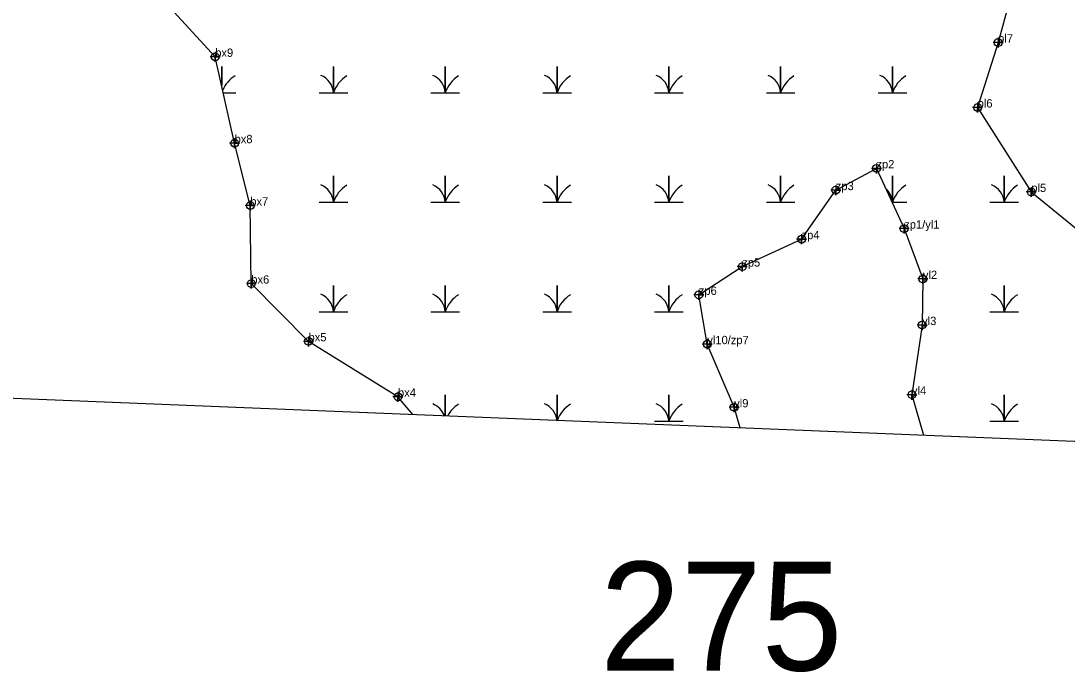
# Model space of a CAD drawing. Extents: x 2071991 to 2268989, y 436479 to 469629.
# Drawn here: x 2233643 to 2234271, y 437646 to 438038 of the extents above; entities that cross this region are included whole.
import ezdxf

# ---------------------------------------------------------------- set-up
doc = ezdxf.new("R2010")
doc.units = 0
for name, color, linetype in [('approx_PSA', 7, 'Continuous'), ('Default', 7, 'Continuous'), ('Exist Environmental Wetland Boundary', 7, 'Continuous'), ('Exist Environmental Wetland Boundary Cogo Comment', 7, 'Continuous'), ('Exist Environmental Wetland Boundary Cogo Point CELL', 7, 'Continuous'), ('Exist Hydro Swamp or Marsh', 7, 'Continuous')]:
    doc.layers.add(name, color=color, linetype=linetype)

msp = doc.modelspace()

# ---------------------------------------------------------------- linework, layer by layer
at = {"layer": 'approx_PSA'}
msp.add_line((2234896.82, 437759.82), (2232283.57, 437865.3), dxfattribs=at)
at = {"layer": 'Exist Environmental Wetland Boundary'}
for points in [[(2234279.17, 438159.32), (2234258.17, 438132.28), (2234242.26, 438069.78), (2234230.04, 438024.51), (2234217.72, 437985.47), (2234249.98, 437934.73), (2234302.96, 437891.47)], [(2233878.1, 437800.94), (2233869.26, 437811.67), (2233815.49, 437844.98), (2233781.11, 437879.68), (2233780.48, 437926.57), (2233771.05, 437964.06), (2233759.41, 438015.96), (2233727.92, 438050.47), (2233767.76, 438077.73), (2233779.58, 438110.39), (2233791.43, 438130.77), (2233736.36, 438122.5), (2233685.39, 438115.35), (2233620.22, 438102.5)], [(2234074.95, 437792.99), (2234071.38, 437805.34), (2234055.2, 437843.29), (2234050.1, 437872.92), (2234076.23, 437889.9), (2234111.89, 437906.38), (2234132.43, 437935.84), (2234156.88, 437948.92), (2234173.58, 437912.73), (2234184.81, 437882.46), (2234184.34, 437854.8), (2234178.23, 437812.94), (2234185.11, 437788.55)]]:
    msp.add_lwpolyline(points, dxfattribs=at)
at = {"layer": 'Exist Environmental Wetland Boundary Cogo Point CELL'}
for points in [[(2234230.04, 438027.51), (2234230.04, 438021.51), (2234230.04, 438024.51), (2234233.04, 438024.51), (2234227.04, 438024.51)], [(2233759.41, 438018.96), (2233759.41, 438012.96), (2233759.41, 438015.96), (2233762.41, 438015.96), (2233756.41, 438015.96)], [(2234217.72, 437988.47), (2234217.72, 437982.47), (2234217.72, 437985.47), (2234220.72, 437985.47), (2234214.72, 437985.47)], [(2233771.05, 437967.06), (2233771.05, 437961.06), (2233771.05, 437964.06), (2233774.05, 437964.06), (2233768.05, 437964.06)], [(2234156.88, 437951.92), (2234156.88, 437945.92), (2234156.88, 437948.92), (2234159.88, 437948.92), (2234153.88, 437948.92)], [(2234132.43, 437938.84), (2234132.43, 437932.84), (2234132.43, 437935.84), (2234135.43, 437935.84), (2234129.43, 437935.84)], [(2234249.98, 437937.73), (2234249.98, 437931.73), (2234249.98, 437934.73), (2234252.98, 437934.73), (2234246.98, 437934.73)], [(2233780.48, 437929.57), (2233780.48, 437923.57), (2233780.48, 437926.57), (2233783.48, 437926.57), (2233777.48, 437926.57)], [(2234173.58, 437915.73), (2234173.58, 437909.73), (2234173.58, 437912.73), (2234176.58, 437912.73), (2234170.58, 437912.73)], [(2234111.89, 437909.38), (2234111.89, 437903.38), (2234111.89, 437906.38), (2234114.89, 437906.38), (2234108.89, 437906.38)], [(2234076.23, 437892.9), (2234076.23, 437886.9), (2234076.23, 437889.9), (2234079.23, 437889.9), (2234073.23, 437889.9)], [(2233781.11, 437882.68), (2233781.11, 437876.68), (2233781.11, 437879.68), (2233784.11, 437879.68), (2233778.11, 437879.68)], [(2234184.81, 437885.46), (2234184.81, 437879.46), (2234184.81, 437882.46), (2234187.81, 437882.46), (2234181.81, 437882.46)], [(2234050.1, 437875.92), (2234050.1, 437869.92), (2234050.1, 437872.92), (2234053.1, 437872.92), (2234047.1, 437872.92)], [(2234184.34, 437857.8), (2234184.34, 437851.8), (2234184.34, 437854.8), (2234187.34, 437854.8), (2234181.34, 437854.8)], [(2233815.49, 437847.98), (2233815.49, 437841.98), (2233815.49, 437844.98), (2233818.49, 437844.98), (2233812.49, 437844.98)], [(2234055.2, 437846.29), (2234055.2, 437840.29), (2234055.2, 437843.29), (2234058.2, 437843.29), (2234052.2, 437843.29)], [(2233869.26, 437814.67), (2233869.26, 437808.67), (2233869.26, 437811.67), (2233872.26, 437811.67), (2233866.26, 437811.67)], [(2234178.23, 437815.94), (2234178.23, 437809.94), (2234178.23, 437812.94), (2234181.23, 437812.94), (2234175.23, 437812.94)], [(2234071.38, 437808.34), (2234071.38, 437802.34), (2234071.38, 437805.34), (2234074.38, 437805.34), (2234068.38, 437805.34)]]:
    msp.add_lwpolyline(points, dxfattribs=at)
for centre in [(2234230.04, 438024.51), (2233759.41, 438015.96), (2234217.72, 437985.47), (2233771.05, 437964.06), (2234156.88, 437948.92), (2234132.43, 437935.84), (2234249.98, 437934.73), (2233780.48, 437926.57), (2234173.58, 437912.73), (2234111.89, 437906.38), (2234076.23, 437889.9), (2233781.11, 437879.68), (2234184.81, 437882.46), (2234050.1, 437872.92), (2234184.34, 437854.8), (2233815.49, 437844.98), (2234055.2, 437843.29), (2233869.26, 437811.67), (2234178.23, 437812.94), (2234071.38, 437805.34)]:
    msp.add_circle(centre, 2.34, dxfattribs=at)
at = {"layer": 'Exist Hydro Swamp or Marsh'}
msp.add_line((2233764.26, 437994.35), (2233771.89, 437994.35), dxfattribs=at)
for points in [[(2233763.28, 437998.69), (2233763.28, 438010.13), (2233763.28, 437998.69)], [(2233821.89, 437994.35), (2233830.49, 437994.35), (2233830.49, 438010.13), (2233830.49, 437994.35), (2233839.09, 437994.35)], [(2233889.09, 437994.35), (2233897.69, 437994.35), (2233897.69, 438010.13), (2233897.69, 437994.35), (2233906.29, 437994.35)], [(2233956.29, 437994.35), (2233964.89, 437994.35), (2233964.89, 438010.13), (2233964.89, 437994.35), (2233973.5, 437994.35)], [(2234023.5, 437994.35), (2234032.1, 437994.35), (2234032.1, 438010.13), (2234032.1, 437994.35), (2234040.7, 437994.35)], [(2234090.7, 437994.35), (2234099.3, 437994.35), (2234099.3, 438010.13), (2234099.3, 437994.35), (2234107.9, 437994.35)], [(2234157.9, 437994.35), (2234166.5, 437994.35), (2234166.5, 438010.13), (2234166.5, 437994.35), (2234175.11, 437994.35)], [(2233821.89, 437928.57), (2233830.49, 437928.57), (2233830.49, 437944.35), (2233830.49, 437928.57), (2233839.09, 437928.57)], [(2233889.09, 437928.57), (2233897.69, 437928.57), (2233897.69, 437944.35), (2233897.69, 437928.57), (2233906.29, 437928.57)], [(2233956.29, 437928.57), (2233964.89, 437928.57), (2233964.89, 437944.35), (2233964.89, 437928.57), (2233973.5, 437928.57)], [(2234023.5, 437928.57), (2234032.1, 437928.57), (2234032.1, 437944.35), (2234032.1, 437928.57), (2234040.7, 437928.57)], [(2234090.7, 437928.57), (2234099.3, 437928.57), (2234099.3, 437944.35), (2234099.3, 437928.57), (2234107.9, 437928.57)], [(2234166.27, 437928.57), (2234166.5, 437928.57), (2234166.5, 437944.35), (2234166.5, 437928.57), (2234175.11, 437928.57)], [(2234225.11, 437928.57), (2234233.71, 437928.57), (2234233.71, 437944.35), (2234233.71, 437928.57), (2234242.31, 437928.57)], [(2233821.89, 437862.79), (2233830.49, 437862.79), (2233830.49, 437878.57), (2233830.49, 437862.79), (2233839.09, 437862.79)], [(2233889.09, 437862.79), (2233897.69, 437862.79), (2233897.69, 437878.57), (2233897.69, 437862.79), (2233906.29, 437862.79)], [(2233956.29, 437862.79), (2233964.89, 437862.79), (2233964.89, 437878.57), (2233964.89, 437862.79), (2233973.5, 437862.79)], [(2234023.5, 437862.79), (2234032.1, 437862.79), (2234032.1, 437878.57), (2234032.1, 437862.79), (2234040.7, 437862.79)], [(2234225.11, 437862.79), (2234233.71, 437862.79), (2234233.71, 437878.57), (2234233.71, 437862.79), (2234242.31, 437862.79)], [(2233897.69, 437800.15), (2233897.69, 437812.79), (2233897.69, 437800.15)], [(2233964.89, 437797.43), (2233964.89, 437812.79), (2233964.89, 437797.43)], [(2234023.5, 437797.01), (2234032.1, 437797.01), (2234032.1, 437812.79), (2234032.1, 437797.01), (2234040.7, 437797.01)], [(2234225.11, 437797.01), (2234233.71, 437797.01), (2234233.71, 437812.79), (2234233.71, 437797.01), (2234242.31, 437797.01)]]:
    msp.add_lwpolyline(points, dxfattribs=at)
for centre, radius, start, end in [((2233781.53, 437988.29), 19.22, 122.12745, 156.50561), ((2233818.22, 437993.46), 12.3, 4.14034, 67.53497), ((2233848.73, 437988.29), 19.22, 122.12745, 161.62219), ((2233885.43, 437993.46), 12.3, 4.14034, 67.53497), ((2233915.93, 437988.29), 19.22, 122.12745, 161.62219), ((2233952.63, 437993.46), 12.3, 4.14034, 67.53497), ((2233983.14, 437988.29), 19.22, 122.12745, 161.62219), ((2234019.83, 437993.46), 12.3, 4.14034, 67.53497), ((2234050.34, 437988.29), 19.22, 122.12745, 161.62219), ((2234087.03, 437993.46), 12.3, 4.14034, 67.53497), ((2234117.54, 437988.29), 19.22, 122.12745, 161.62219), ((2234154.24, 437993.46), 12.3, 4.14034, 67.53497), ((2234184.75, 437988.29), 19.22, 122.12745, 161.62219), ((2233818.22, 437927.68), 12.3, 4.14034, 67.53497), ((2233848.73, 437922.51), 19.22, 122.12745, 161.62219), ((2233885.43, 437927.68), 12.3, 4.14034, 67.53497), ((2233915.93, 437922.51), 19.22, 122.12745, 161.62219), ((2233952.63, 437927.68), 12.3, 4.14034, 67.53497), ((2233983.14, 437922.51), 19.22, 122.12745, 161.62219), ((2234019.83, 437927.68), 12.3, 4.14034, 67.53497), ((2234050.34, 437922.51), 19.22, 122.12745, 161.62219), ((2234087.03, 437927.68), 12.3, 4.14034, 67.53497), ((2234117.54, 437922.51), 19.22, 122.12745, 161.62219), ((2234184.75, 437922.51), 19.22, 122.12745, 161.62219), ((2234221.44, 437927.68), 12.3, 4.14034, 67.53497), ((2234251.95, 437922.51), 19.22, 122.12745, 161.62219), ((2234154.24, 437927.68), 12.3, 4.14034, 48.03518), ((2233818.22, 437861.9), 12.3, 4.14034, 67.53497), ((2233848.73, 437856.73), 19.22, 122.12745, 161.62219), ((2233885.43, 437861.9), 12.3, 4.14034, 67.53497), ((2233915.93, 437856.73), 19.22, 122.12745, 161.62219), ((2233952.63, 437861.9), 12.3, 4.14034, 67.53497), ((2233983.14, 437856.73), 19.22, 122.12745, 161.62219), ((2234019.83, 437861.9), 12.3, 4.14034, 67.53497), ((2234050.34, 437856.73), 19.22, 122.12745, 161.62219), ((2234221.44, 437861.9), 12.3, 4.14034, 67.53497), ((2234251.95, 437856.73), 19.22, 122.12745, 161.62219), ((2233885.43, 437796.12), 12.3, 19.23236, 67.53497), ((2233915.93, 437790.95), 19.22, 122.12745, 151.5976), ((2233952.63, 437796.12), 12.3, 6.13126, 67.53497), ((2233983.14, 437790.95), 19.22, 122.12745, 160.30341), ((2234019.83, 437796.12), 12.3, 4.14034, 67.53497), ((2234050.34, 437790.95), 19.22, 122.12745, 161.62219), ((2234221.44, 437796.12), 12.3, 4.14034, 67.53497), ((2234251.95, 437790.95), 19.22, 122.12745, 161.62219)]:
    msp.add_arc(centre, radius, start, end, dxfattribs=at)

# ---------------------------------------------------------------- texts
at = {"layer": 'Default'}
msp.add_text('275', height=65.34, dxfattribs=at).set_placement((2233990.69, 437647.19))
at = {"layer": 'Exist Environmental Wetland Boundary Cogo Comment'}
for s, p in [('pl7', (2234230.04, 438024.51)), ('bx9', (2233759.41, 438015.96)), ('pl6', (2234217.72, 437985.47)), ('bx8', (2233771.05, 437964.06)), ('zp2', (2234156.88, 437948.92)), ('zp3', (2234132.43, 437935.84)), ('pl5', (2234249.98, 437934.73)), ('bx7', (2233780.48, 437926.57)), ('zp1/yl1', (2234173.58, 437912.73)), ('zp4', (2234111.89, 437906.38)), ('zp5', (2234076.23, 437889.9)), ('yl2', (2234184.81, 437882.46)), ('bx6', (2233781.11, 437879.68)), ('zp6', (2234050.1, 437872.92)), ('yl3', (2234184.34, 437854.8)), ('bx5', (2233815.49, 437844.98)), ('yl10/zp7', (2234055.2, 437843.29)), ('yl4', (2234178.23, 437812.94)), ('bx4', (2233869.26, 437811.67)), ('yl9', (2234071.38, 437805.34))]:
    msp.add_text(s, height=5, dxfattribs=at).set_placement(p)

doc.saveas('drawing.dxf')
